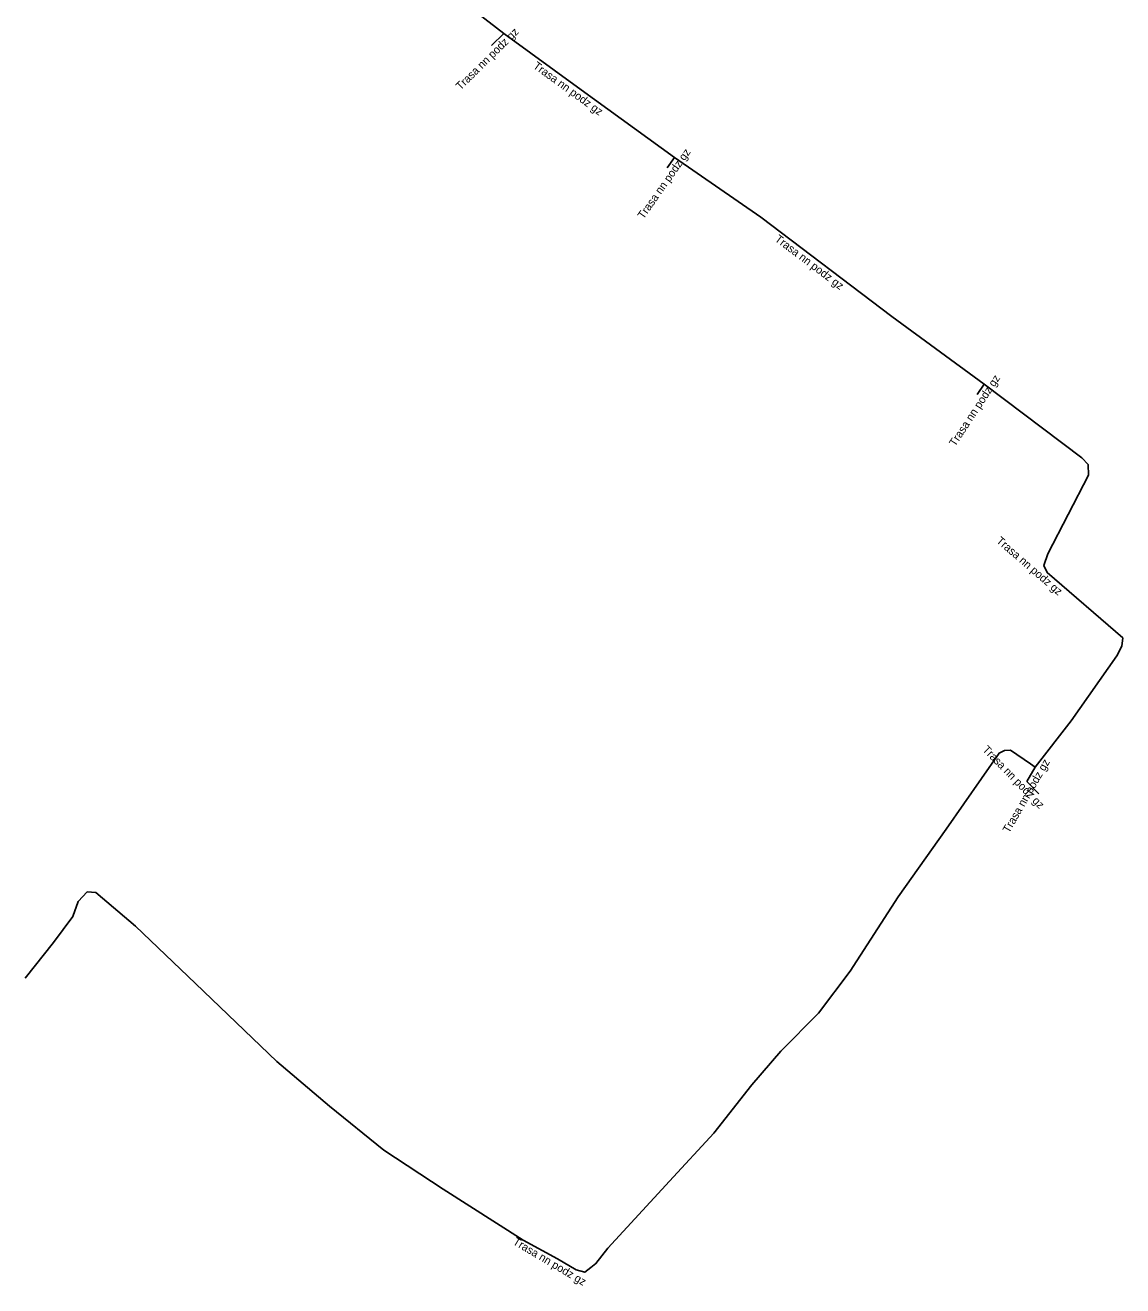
# Model space of a CAD drawing. Extents: x -674518 to -673968, y -1096993 to -1096304.
# Drawn here: x -674036.4 to -673967.8, y -1096940.7 to -1096861.9 of the extents above; entities that cross this region are included whole.
import ezdxf

# ---------------------------------------------------------------- set-up
doc = ezdxf.new("R2010")
doc.units = 0
doc.layers.add('Popiskový text - Ostatní atributy Trasy', color=7, linetype='Continuous')
doc.layers.add('Spojnice NN', color=7, linetype='Continuous')

msp = doc.modelspace()

# ---------------------------------------------------------------- linework, layer by layer
at = {"layer": 'Spojnice NN'}
for points in [[(-674022.28, -1096850.29), (-674019.51, -1096852.55), (-674014.67, -1096856.34), (-674011.39, -1096858.64), (-674006.46, -1096862.46)], [(-674006.46, -1096862.46), (-674007.22, -1096863.21)], [(-674006.46, -1096862.46), (-674001.62, -1096865.99), (-673995.79, -1096870.22)], [(-673995.79, -1096870.22), (-673996.24, -1096870.86)], [(-673995.79, -1096870.22), (-673990.39, -1096873.95), (-673982.21, -1096880.14), (-673976.44, -1096884.38)], [(-673976.44, -1096884.38), (-673976.86, -1096885.02)], [(-673976.44, -1096884.38), (-673970.32, -1096888.99), (-673969.94, -1096889.4), (-673969.92, -1096890.06), (-673972.45, -1096894.99), (-673972.71, -1096895.7), (-673972.5, -1096896.15), (-673967.77, -1096900.23), (-673967.83, -1096900.75), (-673968.14, -1096901.36), (-673971, -1096905.41), (-673973.25, -1096908.32)], [(-673973.25, -1096908.32), (-673973.53, -1096908.1), (-673974.78, -1096907.24), (-673975.16, -1096907.26), (-673975.5, -1096907.43), (-673978.81, -1096912.19), (-673981.81, -1096916.41), (-673984.81, -1096921.06), (-673986.78, -1096923.68), (-673989.14, -1096926.06), (-673990.95, -1096928.16), (-673993.32, -1096931.18), (-673996.1, -1096934.18), (-673999.95, -1096938.38), (-674000.7, -1096939.33), (-674001.02, -1096939.57), (-674001.39, -1096939.88), (-674001.93, -1096939.72), (-674003.09, -1096939.03), (-674005.24, -1096937.88), (-674010.24, -1096934.68), (-674013.95, -1096932.24), (-674017.34, -1096929.5), (-674020.63, -1096926.71), (-674025.72, -1096921.84), (-674029.47, -1096918.25), (-674031.94, -1096916.14), (-674032.48, -1096916.1), (-674033.05, -1096916.7), (-674033.38, -1096917.64), (-674034.6, -1096919.26), (-674036.361, -1096921.506)], [(-673973.25, -1096908.32), (-673973.76, -1096909.21)], [(-673973.76, -1096909.21), (-673973.02, -1096909.97)]]:
    msp.add_lwpolyline(points, dxfattribs=at)

# ---------------------------------------------------------------- texts
at = {"layer": 'Popiskový text - Ostatní atributy Trasy'}
for rotation, p in [(44.62056, (-674009.155, -1096866.033)), (324.03696, (-674004.662, -1096864.586)), (54.88799, (-673997.723, -1096874.099)), (322.88434, (-673989.559, -1096875.394)), (56.72511, (-673978.243, -1096888.311)), (319.21963, (-673975.716, -1096894.235)), (314.2361, (-673976.572, -1096907.254)), (60.18584, (-673974.877, -1096912.467)), (329.25465, (-674005.927, -1096938.098))]:
    msp.add_text('Trasa nn podz gz', height=0.5, rotation=rotation, dxfattribs=at).set_placement(p)

doc.saveas('drawing.dxf')
